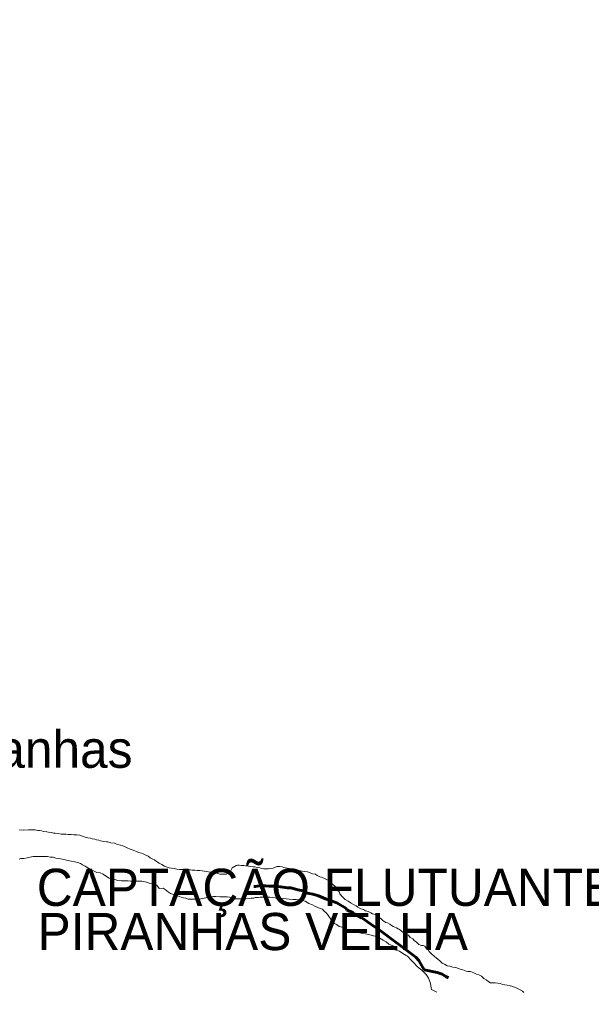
# Model space of a CAD drawing. Extents: x 553962 to 842807, y 8883888 to 9032388.
# Drawn here: x 637529 to 645233, y 8933785 to 8946863 of the extents above; entities that cross this region are included whole.
import ezdxf

# ---------------------------------------------------------------- set-up
doc = ezdxf.new("R2010")
doc.units = 0
doc.header["$LTSCALE"] = 200
doc.linetypes.add('LONG_DASH_SHORT_DASH', pattern=[9.9, 6, -1.2, 1.5, -1.2])
for name, color, linetype, lineweight in [('25', 7, 'Continuous', 13), ('28', 7, 'Continuous', 40), ('41', 7, 'Continuous', 40), ('57', 7, 'Continuous', 13), ('7', 7, 'LONG_DASH_SHORT_DASH', 60), ('9', 7, 'Continuous', 90)]:
    doc.layers.add(name, color=color, linetype=linetype, lineweight=lineweight)

msp = doc.modelspace()

# ---------------------------------------------------------------- linework, layer by layer
at = {"layer": '25'}
for points in [[(637524.6, 8935960.3), (637584.6, 8935954.9), (637652.2, 8935962), (637672.2, 8935961.8), (637694.7, 8935961.7), (637719.7, 8935961.5), (637742.2, 8935958.9), (637777.1, 8935953.6), (637799.7, 8935953.5), (637824.6, 8935945.8), (637859.6, 8935938.1), (637897, 8935932.8), (637922, 8935927.6), (637959.5, 8935922.4), (637989.5, 8935917.2), (638012, 8935914.5)], [(638012, 8935914.5), (638051.9, 8935909.3), (638091.9, 8935904), (638116.9, 8935901.3), (638154.4, 8935901.1), (638186.9, 8935898.3), (638226.9, 8935895.6), (638259.4, 8935895.4), (638281.9, 8935895.2), (638301.9, 8935895.1), (638341.9, 8935887.3), (638376.8, 8935874.6), (638414.2, 8935861.8), (638449.2, 8935851.6), (638486.6, 8935846.3), (638509.1, 8935841.1), (638544.1, 8935835.9), (638566.5, 8935825.7), (638599, 8935820.5), (638621.5, 8935812.9), (638663.9, 8935805.1), (638701.4, 8935799.8), (638721.4, 8935799.7), (638761.3, 8935786.9), (638808.8, 8935779.1), (638851.2, 8935763.8), (638891.1, 8935753.5), (638913.6, 8935750.8), (638951, 8935733.1), (638978.4, 8935717.9), (639020.8, 8935700.1), (639058.2, 8935684.8), (639103.1, 8935669.5), (639130.5, 8935656.8), (639170.4, 8935646.5), (639195.4, 8935636.3), (639232.7, 8935618.6), (639260.2, 8935605.8), (639290, 8935583.1), (639327.4, 8935565.3), (639349.8, 8935555.2), (639374.7, 8935535), (639412, 8935512.2), (639444.4, 8935494.5), (639481.7, 8935471.7), (639519.2, 8935458.9), (639544.1, 8935451.3), (639576.6, 8935443.5), (639614, 8935438.3), (639646.5, 8935433.1), (639686.5, 8935427.8), (639719, 8935425.1), (639739, 8935424.9), (639761.5, 8935424.8), (639784, 8935422.1), (639814, 8935421.9), (639834, 8935421.8), (639856.5, 8935419.1), (639889, 8935416.4), (639921.5, 8935413.7), (639956.5, 8935413.5), (639991.5, 8935408.2), (640021.5, 8935405.5), (640053.9, 8935400.3), (640093.9, 8935392.5), (640126.4, 8935389.8), (640148.9, 8935384.7), (640183.8, 8935376.9), (640233.7, 8935364.2), (640316.3, 8935366), (640339.2, 8935375.1), (640361.5, 8935385.8), (640394.5, 8935450.6), (640447.2, 8935480.3), (640467.3, 8935485.2), (640487.3, 8935485.1), (640514.8, 8935482.4), (640549.8, 8935479.7), (640572.2, 8935474.5), (640607.2, 8935471.8), (640639.7, 8935466.5), (640677.2, 8935463.8), (640699.7, 8935461.1), (640732.2, 8935455.9), (640767.1, 8935450.7), (640789.6, 8935440.5), (640822, 8935435.3), (640842.1, 8935435.2), (640864.6, 8935435), (640884.6, 8935434.9), (640947.2, 8935447), (640994.9, 8935466.7), (641014.9, 8935466.6), (641037.4, 8935466.4), (641067.3, 8935461.2), (641089.8, 8935453.6), (641132.3, 8935445.8), (641167.2, 8935440.5), (641189.7, 8935432.8), (641224.7, 8935427.6), (641259.6, 8935419.9)], [(638992.5, 8935272.2), (638970, 8935272.3), (638925, 8935272.6), (638897.5, 8935275.3), (638855, 8935278.1), (638825, 8935285.8), (638777.6, 8935303.6), (638737.7, 8935311.4), (638700.3, 8935331.7), (638658.1, 8935364.5), (638618.2, 8935382.3), (638573.2, 8935387.6), (638535.8, 8935402.8), (638495.9, 8935423.1), (638451.1, 8935451), (638413.8, 8935471.2), (638376.4, 8935489), (638351.5, 8935506.7), (638314.1, 8935522), (638274.1, 8935529.8), (638224.2, 8935537.6), (638161.8, 8935553), (638086.8, 8935568.6), (638059.4, 8935576.2), (638019.4, 8935581.5), (637982, 8935591.8), (637947, 8935594.5), (637907, 8935599.8), (637884.5, 8935599.9), (637847, 8935600.2), (637827, 8935600.3), (637792, 8935600.5), (637754.5, 8935600.8), (637714.4, 8935601.1), (637691.9, 8935596.2), (637654.3, 8935588.9), (637631.8, 8935584.1), (637591.7, 8935576.8), (637549.2, 8935574.6), (637524.1, 8935567.3)], [(641259.6, 8935419.9), (641294.6, 8935414.6), (641334.5, 8935404.4), (641369.5, 8935399.1), (641409.5, 8935393.8), (641441.9, 8935383.6), (641474.3, 8935368.4), (641514.3, 8935363.1), (641536.7, 8935345.4), (641574.1, 8935330.2), (641596.6, 8935325), (641636.4, 8935307.2), (641673.8, 8935289.5), (641708.7, 8935271.7), (641748.3, 8935223.9), (641798.1, 8935183.5), (641812.8, 8935148.3), (641832.6, 8935125.7), (641842.5, 8935100.6), (641872.2, 8935067.8), (641894.6, 8935047.7), (641916.9, 8935022.5), (641954.2, 8935002.2), (641994, 8934971.9), (642028.9, 8934954.1), (642063.8, 8934936.4), (642086.2, 8934918.7), (642126, 8934898.4), (642161, 8934890.7), (642188.4, 8934873), (642225.8, 8934860.2), (642260.7, 8934842.4), (642283.1, 8934832.3), (642318, 8934819.5), (642340.5, 8934811.9), (642357.8, 8934791.7), (642395.2, 8934769), (642427.4, 8934736.2), (642462.3, 8934715.9), (642484.8, 8934708.3), (642517.1, 8934690.5), (642539.5, 8934675.4), (642561.9, 8934660.2), (642604.3, 8934642.4), (642661.6, 8934609.5), (642711.2, 8934564.1), (642766.1, 8934543.7), (642790.9, 8934513.5), (642825.8, 8934495.7), (642845.6, 8934470.6), (642875.5, 8934450.3), (642907.7, 8934417.6), (642942.6, 8934402.3), (642965.1, 8934402.2), (642987.6, 8934394.5), (643004.9, 8934366.9), (643027.3, 8934356.7), (643044.6, 8934324), (643084.3, 8934286.2), (643146.4, 8934233.2), (643183.7, 8934202.9), (643221, 8934167.7), (643253.4, 8934152.4), (643288.2, 8934132.2), (643323.2, 8934124.4), (643363.1, 8934114.1), (643405.6, 8934108.8), (643440.5, 8934096.1), (643477.9, 8934083.3), (643500.4, 8934075.7), (643542.8, 8934060.4), (643567.8, 8934055.2), (643602.8, 8934052.5), (643647.6, 8934034.7), (643685, 8934019.4), (643717.5, 8934009.2), (643749.9, 8933993.9), (643784.6, 8933958.6), (643814.5, 8933943.4), (643836.9, 8933925.7), (643871.7, 8933903), (643899.2, 8933902.8), (643936.7, 8933900.1), (643971.7, 8933897.3), (644004.2, 8933892.1), (644026.7, 8933884.4), (644066.6, 8933876.7), (644096.6, 8933868.9), (644136.6, 8933863.7), (644161.5, 8933856), (644196.4, 8933843.2), (644226.3, 8933830.5), (644263.7, 8933810.3), (644301.1, 8933790), (644323.4, 8933772.3)], [(642690, 8934297.2), (642645.2, 8934327.5), (642587.9, 8934347.9), (642556.4, 8934400.2), (642504.8, 8934424.3), (642466.9, 8934451.8), (642425.6, 8934475.9), (642384.3, 8934503.4), (642339.5, 8934524.1), (642294.8, 8934534.4), (642294.8, 8934534.4), (642246.6, 8934548.2), (642188.1, 8934561.9), (642151.8, 8934566.1), (642086.9, 8934579), (642032, 8934596.9), (641994.6, 8934612.2), (641952.2, 8934620), (641902.2, 8934635.3), (641874.9, 8934653.1), (641834.9, 8934658.3), (641800.1, 8934686.1), (641770.2, 8934701.3), (641755.4, 8934726.4), (641723.1, 8934756.7), (641698.3, 8934789.4), (641681, 8934817.1), (641663.7, 8934837.2), (641628.9, 8934872.5), (641609.1, 8934892.6), (641558.1, 8934912.8), (641506.5, 8934933.5), (641473.6, 8934950.3), (641426.3, 8934968.1), (641376.5, 8935001), (641329.1, 8935016.3), (641301.6, 8935019), (641254.1, 8935021.8), (641209.1, 8935024.7), (641159.1, 8935027.5), (641081.6, 8935035.5), (641021.6, 8935040.9), (640971.7, 8935046.2), (640936.7, 8935051.5), (640899.2, 8935054.2), (640864.2, 8935054.5), (640841.7, 8935054.6), (640806.6, 8935054.8), (640769.1, 8935052.6), (640744.1, 8935050.3), (640704, 8935048), (640684, 8935043.2), (640649, 8935040.9), (640621.4, 8935036.1), (640578.9, 8935033.8), (640543.8, 8935031.6), (640498.8, 8935031.8), (640471.3, 8935032), (640451.3, 8935032.2), (640431.3, 8935032.3), (640393.9, 8935042.6), (640358.9, 8935052.8), (640326.5, 8935058), (640229.1, 8935058.3), (640168.9, 8935061.6), (640141.4, 8935061.8), (640098.9, 8935059.5), (640076.3, 8935052.2), (640041.2, 8935047.4), (640016.2, 8935040.1), (639971.1, 8935032.8), (639951.1, 8935028), (639898.5, 8935025.8), (639856, 8935026.1), (639833.5, 8935026.2), (639801, 8935029), (639768.6, 8935039.2), (639738.6, 8935044.4), (639708.7, 8935054.6), (639686.2, 8935062.3), (639663.8, 8935072.4), (639628.9, 8935085.2), (639601.4, 8935090.4), (639564, 8935105.6), (639536.6, 8935120.8), (639511.7, 8935141), (639489.3, 8935158.7), (639464.5, 8935173.9), (639409.4, 8935171.8), (639379.8, 8935217), (639342.3, 8935227.3), (639317.4, 8935234.9), (639274.9, 8935242.7), (639240, 8935255.5), (639202.5, 8935263.2), (639177.6, 8935270.9), (639125.1, 8935271.3), (639090, 8935271.5), (639050, 8935271.8), (639030, 8935271.9), (638992.5, 8935272.2)], [(643148, 8933777.6), (643078.2, 8933813.1), (643066.3, 8933890.8), (643056.5, 8933918.4), (643046.7, 8933941), (643039.3, 8933966.1), (643022, 8933986.2), (643004.7, 8934016.4), (642970, 8934051.7), (642947.6, 8934071.8), (642910.3, 8934099.6), (642880.5, 8934127.3), (642842.1, 8934169.7), (642842.1, 8934169.7), (642804.3, 8934207.6), (642755, 8934260.3), (642734.8, 8934269.3), (642690, 8934297.2)]]:
    msp.add_lwpolyline(points, dxfattribs=at)
at = {"layer": '57'}
for points in [[(637524.6, 8935960.3), (637584.6, 8935954.9), (637652.2, 8935962), (637672.2, 8935961.8), (637694.7, 8935961.7), (637719.7, 8935961.5), (637742.2, 8935958.9), (637777.1, 8935953.6), (637799.7, 8935953.5), (637824.6, 8935945.8), (637859.6, 8935938.1), (637897, 8935932.8), (637922, 8935927.6), (637959.5, 8935922.4), (637989.5, 8935917.2), (638012, 8935914.5)], [(637524.6, 8935960.3), (637584.6, 8935954.9), (637652.2, 8935962), (637672.2, 8935961.8), (637694.7, 8935961.7), (637719.7, 8935961.5), (637742.2, 8935958.9), (637777.1, 8935953.6), (637799.7, 8935953.5), (637824.6, 8935945.8), (637859.6, 8935938.1), (637897, 8935932.8), (637922, 8935927.6), (637959.5, 8935922.4), (637989.5, 8935917.2), (638012, 8935914.5)], [(638012, 8935914.5), (638051.9, 8935909.3), (638091.9, 8935904), (638116.9, 8935901.3), (638154.4, 8935901.1), (638186.9, 8935898.3), (638226.9, 8935895.6), (638259.4, 8935895.4), (638281.9, 8935895.2), (638301.9, 8935895.1), (638341.9, 8935887.3), (638376.8, 8935874.6), (638414.2, 8935861.8), (638449.2, 8935851.6), (638486.6, 8935846.3), (638509.1, 8935841.1), (638544.1, 8935835.9), (638566.5, 8935825.7), (638599, 8935820.5), (638621.5, 8935812.9), (638663.9, 8935805.1), (638701.4, 8935799.8), (638721.4, 8935799.7), (638761.3, 8935786.9), (638808.8, 8935779.1), (638851.2, 8935763.8), (638891.1, 8935753.5), (638913.6, 8935750.8), (638951, 8935733.1), (638978.4, 8935717.9), (639020.8, 8935700.1), (639058.2, 8935684.8), (639103.1, 8935669.5), (639130.5, 8935656.8), (639170.4, 8935646.5), (639195.4, 8935636.3), (639232.7, 8935618.6), (639260.2, 8935605.8), (639290, 8935583.1), (639327.4, 8935565.3), (639349.8, 8935555.2), (639374.7, 8935535), (639412, 8935512.2), (639444.4, 8935494.5), (639481.7, 8935471.7), (639519.2, 8935458.9), (639544.1, 8935451.3), (639576.6, 8935443.5), (639614, 8935438.3), (639646.5, 8935433.1), (639686.5, 8935427.8), (639719, 8935425.1), (639739, 8935424.9), (639761.5, 8935424.8), (639784, 8935422.1), (639814, 8935421.9), (639834, 8935421.8), (639856.5, 8935419.1), (639889, 8935416.4), (639921.5, 8935413.7), (639956.5, 8935413.5), (639991.5, 8935408.2), (640021.5, 8935405.5), (640053.9, 8935400.3), (640093.9, 8935392.5), (640126.4, 8935389.8), (640148.9, 8935384.7), (640183.8, 8935376.9), (640233.7, 8935364.2), (640316.3, 8935366), (640339.2, 8935375.1), (640361.5, 8935385.8), (640394.5, 8935450.6), (640447.2, 8935480.3), (640467.3, 8935485.2), (640487.3, 8935485.1), (640514.8, 8935482.4), (640549.8, 8935479.7), (640572.2, 8935474.5), (640607.2, 8935471.8), (640639.7, 8935466.5), (640677.2, 8935463.8), (640699.7, 8935461.1), (640732.2, 8935455.9), (640767.1, 8935450.7), (640789.6, 8935440.5), (640822, 8935435.3), (640842.1, 8935435.2), (640864.6, 8935435), (640884.6, 8935434.9), (640947.2, 8935447), (640994.9, 8935466.7), (641014.9, 8935466.6), (641037.4, 8935466.4), (641067.3, 8935461.2), (641089.8, 8935453.6), (641132.3, 8935445.8), (641167.2, 8935440.5), (641189.7, 8935432.8), (641224.7, 8935427.6), (641259.6, 8935419.9)], [(638012, 8935914.5), (638051.9, 8935909.3), (638091.9, 8935904), (638116.9, 8935901.3), (638154.4, 8935901.1), (638186.9, 8935898.3), (638226.9, 8935895.6), (638259.4, 8935895.4), (638281.9, 8935895.2), (638301.9, 8935895.1), (638341.9, 8935887.3), (638376.8, 8935874.6), (638414.2, 8935861.8), (638449.2, 8935851.6), (638486.6, 8935846.3), (638509.1, 8935841.1), (638544.1, 8935835.9), (638566.5, 8935825.7), (638599, 8935820.5), (638621.5, 8935812.9), (638663.9, 8935805.1), (638701.4, 8935799.8), (638721.4, 8935799.7), (638761.3, 8935786.9), (638808.8, 8935779.1), (638851.2, 8935763.8), (638891.1, 8935753.5), (638913.6, 8935750.8), (638951, 8935733.1), (638978.4, 8935717.9), (639020.8, 8935700.1), (639058.2, 8935684.8), (639103.1, 8935669.5), (639130.5, 8935656.8), (639170.4, 8935646.5), (639195.4, 8935636.3), (639232.7, 8935618.6), (639260.2, 8935605.8), (639290, 8935583.1), (639327.4, 8935565.3), (639349.8, 8935555.2), (639374.7, 8935535), (639412, 8935512.2), (639444.4, 8935494.5), (639481.7, 8935471.7), (639519.2, 8935458.9), (639544.1, 8935451.3), (639576.6, 8935443.5), (639614, 8935438.3), (639646.5, 8935433.1), (639686.5, 8935427.8), (639719, 8935425.1), (639739, 8935424.9), (639761.5, 8935424.8), (639784, 8935422.1), (639814, 8935421.9), (639834, 8935421.8), (639856.5, 8935419.1), (639889, 8935416.4), (639921.5, 8935413.7), (639956.5, 8935413.5), (639991.5, 8935408.2), (640021.5, 8935405.5), (640053.9, 8935400.3), (640093.9, 8935392.5), (640126.4, 8935389.8), (640148.9, 8935384.7), (640183.8, 8935376.9), (640233.7, 8935364.2), (640316.3, 8935366), (640339.2, 8935375.1), (640361.5, 8935385.8), (640394.5, 8935450.6), (640447.2, 8935480.3), (640467.3, 8935485.2), (640487.3, 8935485.1), (640514.8, 8935482.4), (640549.8, 8935479.7), (640572.2, 8935474.5), (640607.2, 8935471.8), (640639.7, 8935466.5), (640677.2, 8935463.8), (640699.7, 8935461.1), (640732.2, 8935455.9), (640767.1, 8935450.7), (640789.6, 8935440.5), (640822, 8935435.3), (640842.1, 8935435.2), (640864.6, 8935435), (640884.6, 8935434.9), (640947.2, 8935447), (640994.9, 8935466.7), (641014.9, 8935466.6), (641037.4, 8935466.4), (641067.3, 8935461.2), (641089.8, 8935453.6), (641132.3, 8935445.8), (641167.2, 8935440.5), (641189.7, 8935432.8), (641224.7, 8935427.6), (641259.6, 8935419.9)], [(641259.6, 8935419.9), (641294.6, 8935414.6), (641334.5, 8935404.4), (641369.5, 8935399.1), (641409.5, 8935393.8), (641441.9, 8935383.6), (641474.3, 8935368.4), (641514.3, 8935363.1), (641536.7, 8935345.4), (641574.1, 8935330.2), (641596.6, 8935325), (641636.4, 8935307.2), (641673.8, 8935289.5), (641708.7, 8935271.7), (641748.3, 8935223.9), (641798.1, 8935183.5), (641812.8, 8935148.3), (641832.6, 8935125.7), (641842.5, 8935100.6), (641872.2, 8935067.8), (641894.6, 8935047.7), (641916.9, 8935022.5), (641954.2, 8935002.2), (641994, 8934971.9), (642028.9, 8934954.1), (642063.8, 8934936.4), (642086.2, 8934918.7), (642126, 8934898.4), (642161, 8934890.7), (642188.4, 8934873), (642225.8, 8934860.2), (642260.7, 8934842.4), (642283.1, 8934832.3), (642318, 8934819.5), (642340.5, 8934811.9), (642357.8, 8934791.7), (642395.2, 8934769), (642427.4, 8934736.2), (642462.3, 8934715.9), (642484.8, 8934708.3), (642517.1, 8934690.5), (642539.5, 8934675.4), (642561.9, 8934660.2), (642604.3, 8934642.4), (642661.6, 8934609.5), (642711.2, 8934564.1), (642766.1, 8934543.7), (642790.9, 8934513.5), (642825.8, 8934495.7), (642845.6, 8934470.6), (642875.5, 8934450.3), (642907.7, 8934417.6), (642942.6, 8934402.3), (642965.1, 8934402.2), (642987.6, 8934394.5), (643004.9, 8934366.9), (643027.3, 8934356.7), (643044.6, 8934324), (643084.3, 8934286.2), (643146.4, 8934233.2), (643183.7, 8934202.9), (643221, 8934167.7), (643253.4, 8934152.4), (643288.2, 8934132.2), (643323.2, 8934124.4), (643363.1, 8934114.1), (643405.6, 8934108.8), (643440.5, 8934096.1), (643477.9, 8934083.3), (643500.4, 8934075.7), (643542.8, 8934060.4), (643567.8, 8934055.2), (643602.8, 8934052.5), (643647.6, 8934034.7), (643685, 8934019.4), (643717.5, 8934009.2), (643749.9, 8933993.9), (643784.6, 8933958.6), (643814.5, 8933943.4), (643836.9, 8933925.7), (643871.7, 8933903), (643899.2, 8933902.8), (643936.7, 8933900.1), (643971.7, 8933897.3), (644004.2, 8933892.1), (644026.7, 8933884.4), (644066.6, 8933876.7), (644096.6, 8933868.9), (644136.6, 8933863.7), (644161.5, 8933856), (644196.4, 8933843.2), (644226.3, 8933830.5), (644263.7, 8933810.3), (644301.1, 8933790), (644323.4, 8933772.3)], [(641259.6, 8935419.9), (641294.6, 8935414.6), (641334.5, 8935404.4), (641369.5, 8935399.1), (641409.5, 8935393.8), (641441.9, 8935383.6), (641474.3, 8935368.4), (641514.3, 8935363.1), (641536.7, 8935345.4), (641574.1, 8935330.2), (641596.6, 8935325), (641636.4, 8935307.2), (641673.8, 8935289.5), (641708.7, 8935271.7), (641748.3, 8935223.9), (641798.1, 8935183.5), (641812.8, 8935148.3), (641832.6, 8935125.7), (641842.5, 8935100.6), (641872.2, 8935067.8), (641894.6, 8935047.7), (641916.9, 8935022.5), (641954.2, 8935002.2), (641994, 8934971.9), (642028.9, 8934954.1), (642063.8, 8934936.4), (642086.2, 8934918.7), (642126, 8934898.4), (642161, 8934890.7), (642188.4, 8934873), (642225.8, 8934860.2), (642260.7, 8934842.4), (642283.1, 8934832.3), (642318, 8934819.5), (642340.5, 8934811.9), (642357.8, 8934791.7), (642395.2, 8934769), (642427.4, 8934736.2), (642462.3, 8934715.9), (642484.8, 8934708.3), (642517.1, 8934690.5), (642539.5, 8934675.4), (642561.9, 8934660.2), (642604.3, 8934642.4), (642661.6, 8934609.5), (642711.2, 8934564.1), (642766.1, 8934543.7), (642790.9, 8934513.5), (642825.8, 8934495.7), (642845.6, 8934470.6), (642875.5, 8934450.3), (642907.7, 8934417.6), (642942.6, 8934402.3), (642965.1, 8934402.2), (642987.6, 8934394.5), (643004.9, 8934366.9), (643027.3, 8934356.7), (643044.6, 8934324), (643084.3, 8934286.2), (643146.4, 8934233.2), (643183.7, 8934202.9), (643221, 8934167.7), (643253.4, 8934152.4), (643288.2, 8934132.2), (643323.2, 8934124.4), (643363.1, 8934114.1), (643405.6, 8934108.8), (643440.5, 8934096.1), (643477.9, 8934083.3), (643500.4, 8934075.7), (643542.8, 8934060.4), (643567.8, 8934055.2), (643602.8, 8934052.5), (643647.6, 8934034.7), (643685, 8934019.4), (643717.5, 8934009.2), (643749.9, 8933993.9), (643784.6, 8933958.6), (643814.5, 8933943.4), (643836.9, 8933925.7), (643871.7, 8933903), (643899.2, 8933902.8), (643936.7, 8933900.1), (643971.7, 8933897.3), (644004.2, 8933892.1), (644026.7, 8933884.4), (644066.6, 8933876.7), (644096.6, 8933868.9), (644136.6, 8933863.7), (644161.5, 8933856), (644196.4, 8933843.2), (644226.3, 8933830.5), (644263.7, 8933810.3), (644301.1, 8933790), (644323.4, 8933772.3)]]:
    msp.add_lwpolyline(points, dxfattribs=at)
at = {"layer": '7'}
for points in [[(641349.5, 8935138.5), (641279.6, 8935153.8), (641232.2, 8935166.6), (641182.2, 8935179.4), (641137.2, 8935182.1), (641014.8, 8935197.8), (640987.4, 8935200.4), (640937.4, 8935200.7), (640887.4, 8935203.5), (640847.4, 8935206.2), (640824.9, 8935206.3), (640794.9, 8935206.5), (640772.4, 8935206.6), (640732.4, 8935204.3), (640707.4, 8935199.4), (640683.2, 8935198.4)], [(643306.9, 8933971.4), (643271.7, 8933987.2), (643222, 8934017.5), (643154.6, 8934040.4), (642977.3, 8934076.3), (642905.7, 8934204.3), (642868.5, 8934249.6), (642368.5, 8934617.6), (642318.7, 8934652.9), (642216.7, 8934723.5), (642166.9, 8934758.8), (642137, 8934776.5), (642047.4, 8934827), (642025, 8934842.1), (641937.8, 8934885.1), (641922.9, 8934907.7), (641800.9, 8934978.4), (641648.8, 8935034.3), (641556.5, 8935072.3), (641479.2, 8935095.2), (641381.8, 8935110.8), (641349.5, 8935138.5)]]:
    msp.add_lwpolyline(points, dxfattribs=at)
at = {"layer": '9'}
msp.add_spline([(637260.6, 8972975.8), (641524.5, 8971056.2), (652526.1, 8965412.7), (653164.3, 8965062.8), (670790.5, 8953770.1), (686194, 8943929.9), (696283.3, 8937647.1)], degree=3, dxfattribs=at)

# ---------------------------------------------------------------- texts
at = {"layer": '28'}
for s, p in [('CAPTAÇÃO FLUTUANTE', (637762.9, 8934937.1)), ('PIRANHAS VELHA', (637772.9, 8934342.2))]:
    msp.add_text(s, height=500, dxfattribs=at).set_placement(p)
at = {"layer": '41'}
msp.add_text('Piranhas', height=500, dxfattribs=at).set_placement((636412.8, 8936794.9))

doc.saveas('drawing.dxf')
